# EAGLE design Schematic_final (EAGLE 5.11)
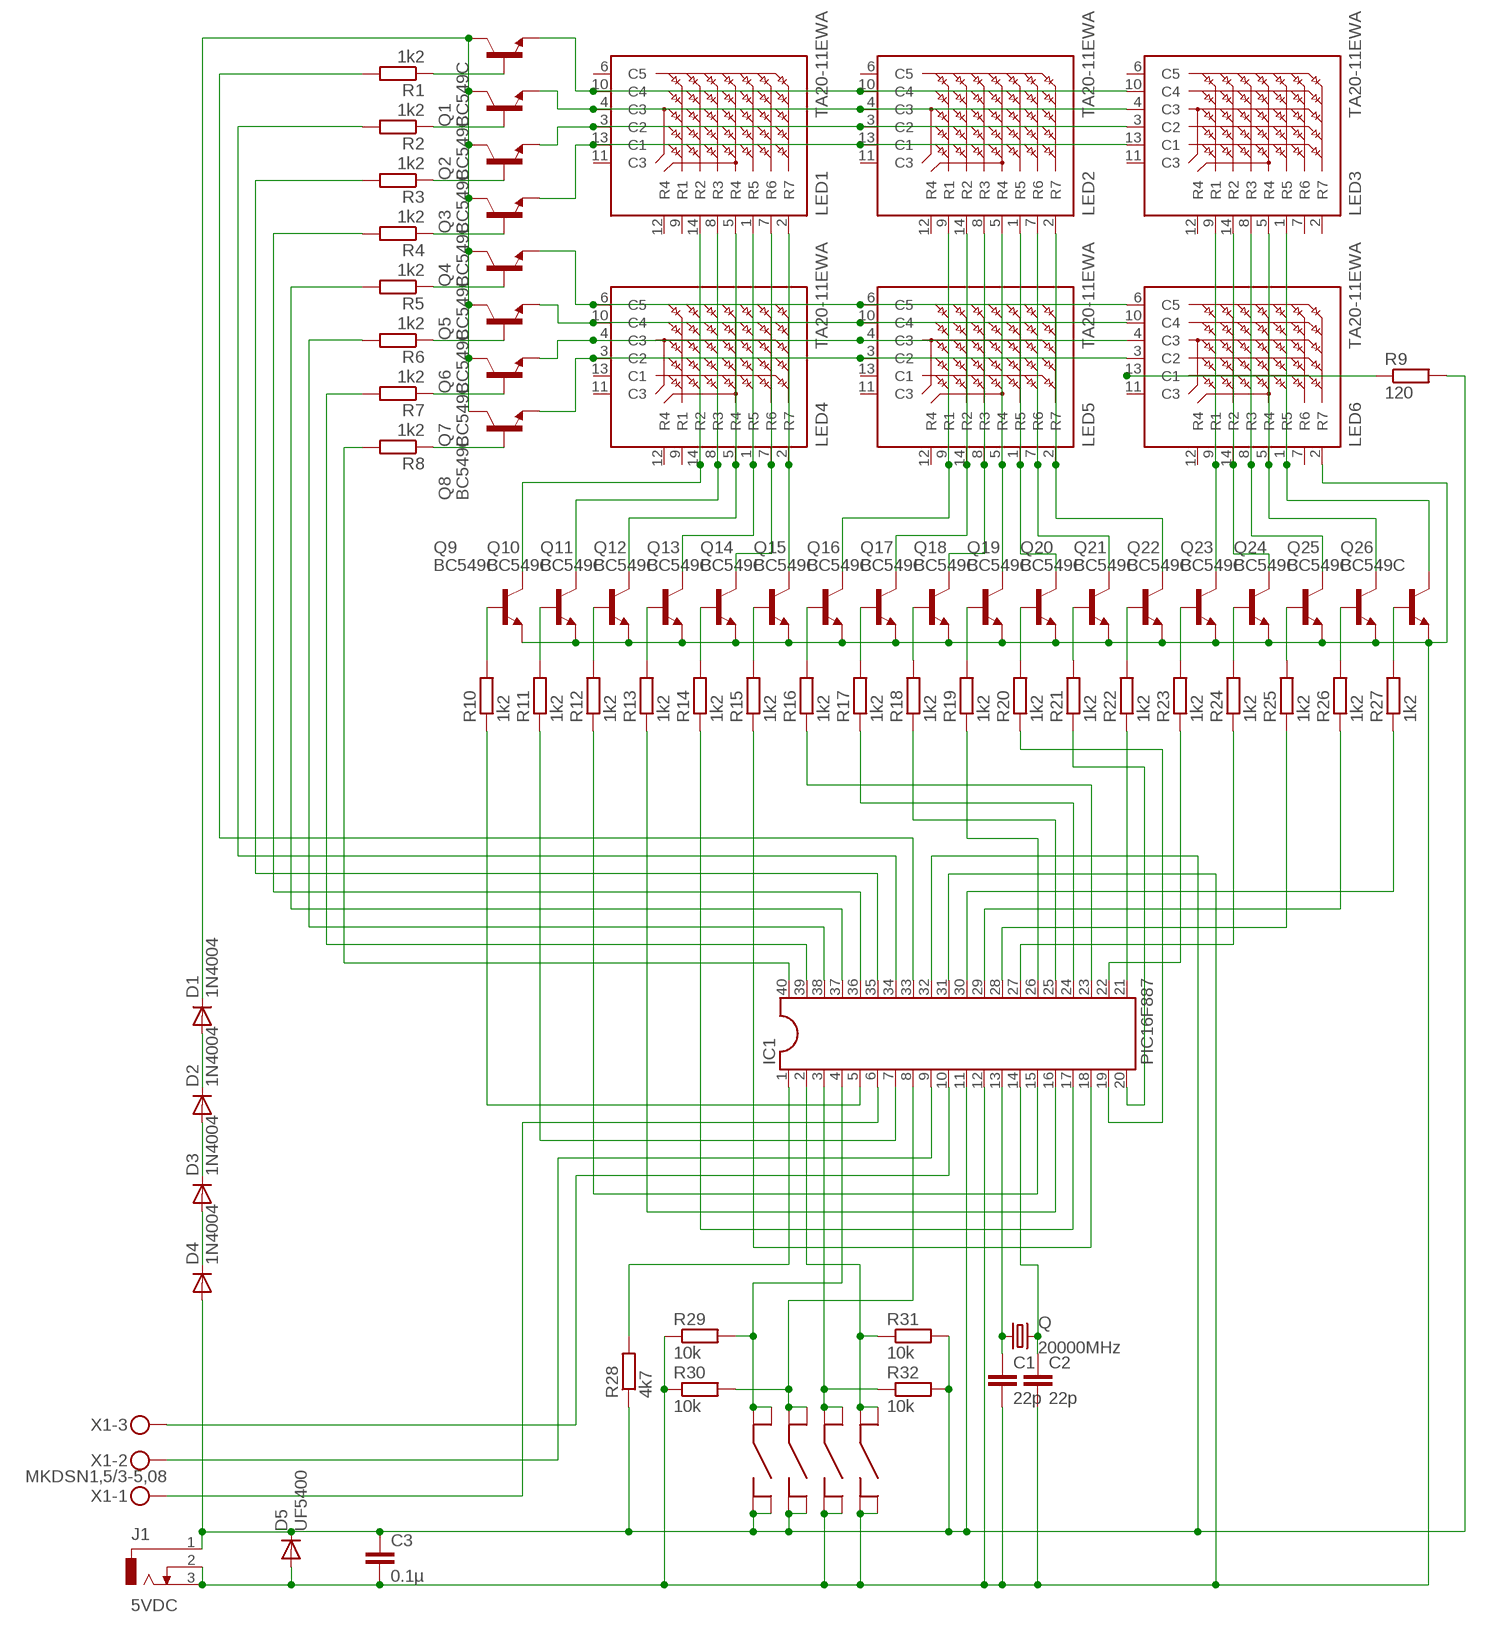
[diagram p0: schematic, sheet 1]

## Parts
C1  22p  C-EU025-025X050  [C025-025X050]
C2  22p  C-EU025-025X050  [C025-025X050]
C3  0.1µ  C-EU050-035X075  [C050-035X075]
D1  1N4004  [DO41-10]
D2  1N4004  [DO41-10]
D3  1N4004  [DO41-10]
D4  1N4004  [DO41-10]
D5  UF5400  [DO201-15]
IC1  PIC16F887  DIL40  [DIL40]
J1  5VDC  DCJ0303  [DCJ0303]
LED1  TA20-11EWA  [TA20-11HWA]
LED2  TA20-11EWA  [TA20-11HWA]
LED3  TA20-11EWA  [TA20-11HWA]
LED4  TA20-11EWA  [TA20-11HWA]
LED5  TA20-11EWA  [TA20-11HWA]
LED6  TA20-11EWA  [TA20-11HWA]
Q  20000MHz  CRYSTALHC49U-V  [HC49U-V]
Q1  BC549C  [TO92-EBC]
Q2  BC549C  [TO92-EBC]
Q3  BC549C  [TO92-EBC]
Q4  BC549C  [TO92-EBC]
Q5  BC549C  [TO92-EBC]
Q6  BC549C  [TO92-EBC]
Q7  BC549C  [TO92-EBC]
Q8  BC549C  [TO92-EBC]
Q9  BC549C  [TO92-EBC]
Q10  BC549C  [TO92-EBC]
Q11  BC549C  [TO92-EBC]
Q12  BC549C  [TO92-EBC]
Q13  BC549C  [TO92-EBC]
Q14  BC549C  [TO92-EBC]
Q15  BC549C  [TO92-EBC]
Q16  BC549C  [TO92-EBC]
Q17  BC549C  [TO92-EBC]
Q18  BC549C  [TO92-EBC]
Q19  BC549C  [TO92-EBC]
Q20  BC549C  [TO92-EBC]
Q21  BC549C  [TO92-EBC]
Q22  BC549C  [TO92-EBC]
Q23  BC549C  [TO92-EBC]
Q24  BC549C  [TO92-EBC]
Q25  BC549C  [TO92-EBC]
Q26  BC549C  [TO92-EBC]
R1  1k2  R-EU_0207/12  [0207/12]
R2  1k2  R-EU_0207/12  [0207/12]
R3  1k2  R-EU_0207/12  [0207/12]
R4  1k2  R-EU_0207/12  [0207/12]
R5  1k2  R-EU_0207/12  [0207/12]
R6  1k2  R-EU_0207/12  [0207/12]
R7  1k2  R-EU_0207/12  [0207/12]
R8  1k2  R-EU_0207/12  [0207/12]
R9  120  R-EU_0207/12  [0207/12]
R10  1k2  R-EU_0207/12  [0207/12]
R11  1k2  R-EU_0207/12  [0207/12]
R12  1k2  R-EU_0207/12  [0207/12]
R13  1k2  R-EU_0207/12  [0207/12]
R14  1k2  R-EU_0207/12  [0207/12]
R15  1k2  R-EU_0207/12  [0207/12]
R16  1k2  R-EU_0207/12  [0207/12]
R17  1k2  R-EU_0207/12  [0207/12]
R18  1k2  R-EU_0207/12  [0207/12]
R19  1k2  R-EU_0207/12  [0207/12]
R20  1k2  R-EU_0207/12  [0207/12]
R21  1k2  R-EU_0207/12  [0207/12]
R22  1k2  R-EU_0207/12  [0207/12]
R23  1k2  R-EU_0207/12  [0207/12]
R24  1k2  R-EU_0207/12  [0207/12]
R25  1k2  R-EU_0207/12  [0207/12]
R26  1k2  R-EU_0207/12  [0207/12]
R27  1k2  R-EU_0207/12  [0207/12]
R28  4k7  R-EU_0207/10  [0207/10]
R29  10k  R-EU_0207/10  [0207/10]
R30  10k  R-EU_0207/10  [0207/10]
R31  10k  R-EU_0207/10  [0207/10]
R32  10k  R-EU_0207/10  [0207/10]
S1  DRUKKNOP  [DRUKKNOP]
S2  DRUKKNOP  [DRUKKNOP]
S3  DRUKKNOP  [DRUKKNOP]
S4  DRUKKNOP  [DRUKKNOP]
X1  MKDSN1,5/3-5,08  [MKDSN1,5/3-5,08]

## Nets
GND: C3.1 D4.A D5.C IC1.11 IC1.32 J1.1 R9.2 R28.1 R31.2 R32.2 S1.P$2 S1.P$4 S2.P$2 S2.P$4
N$1: IC1.5 R10.1
N$2: IC1.7 R11.1
N$3: IC1.16 R13.1
N$4: IC1.15 R12.1
N$5: IC1.17 R14.1
N$6: IC1.18 R15.1
N$7: IC1.23 R16.1
N$8: IC1.24 R17.1
N$9: LED2.5(R4) LED5.5(R4) Q18.C
N$10: LED2.8(R3) LED5.8(R3) Q17.C
N$11: LED2.1(R5) LED5.1(R5) Q19.C
N$12: LED2.14(R2) LED5.14(R2) Q16.C
N$13: LED2.9(R1) LED5.9(R1) Q15.C
N$14: LED2.7(R6) LED5.7(R6) Q20.C
N$15: LED2.2(R7) LED5.2(R7) Q21.C
N$16: LED3.9(R1) LED6.9(R1) Q22.C
N$17: LED3.14(R2) LED6.14(R2) Q23.C
N$18: LED3.8(R3) LED6.8(R3) Q24.C
N$19: LED3.5(R4) LED6.5(R4) Q25.C
N$20: LED3.1(R5) LED6.1(R5) Q26.C
N$21: LED1.2(R7) LED4.2(R7) Q14.C
N$22: LED1.7(R6) LED4.7(R6) Q13.C
N$23: LED1.1(R5) LED4.1(R5) Q12.C
N$24: LED1.5(R4) LED4.5(R4) Q11.C
N$25: LED1.8(R3) LED4.8(R3) Q10.C
N$26: LED1.14(R2) LED4.14(R2) Q9.C
N$27: IC1.25 R18.1
N$28: IC1.19 R20.1
N$29: IC1.20 R21.1
N$30: IC1.26 R19.1
N$31: IC1.21 R22.1
N$32: IC1.22 R23.1
N$33: IC1.27 R24.1
N$34: IC1.28 R25.1
N$35: IC1.29 R26.1
N$36: IC1.30 R27.1
N$37: Q9.B R10.2
N$38: Q17.B R18.2
N$39: Q10.B R11.2
N$40: Q11.B R12.2
N$41: Q12.B R13.2
N$42: Q13.B R14.2
N$43: Q14.B R15.2
N$44: Q15.B R16.2
N$45: Q16.B R17.2
N$46: Q18.B R19.2
N$47: Q19.B R20.2
N$48: Q20.B R21.2
N$49: Q21.B R22.2
N$50: Q22.B R23.2
N$51: Q23.B R24.2
N$52: Q24.B R25.2
N$53: Q25.B R26.2
N$54: Q26.B R27.2
N$55: IC1.1 R28.2
N$56: LED6.13(C1) R9.1
N$57: LED1.10(C4) LED2.10(C4) LED3.10(C4) Q1.E
N$58: LED1.4(C3) LED2.4(C3) LED3.4(C3) Q2.E
N$59: LED1.3(C2) LED2.3(C2) LED3.3(C2) Q3.E
N$60: LED1.13(C1) LED2.13(C1) LED3.13(C1) Q4.E
N$61: LED4.6(C5) LED5.6(C5) LED6.6(C5) Q5.E
N$62: LED4.3(C2) LED5.3(C2) LED6.3(C2) Q8.E
N$63: LED4.4(C3) LED5.4(C3) LED6.4(C3) Q7.E
N$64: LED4.10(C4) LED5.10(C4) LED6.10(C4) Q6.E
N$65: IC1.38 R6.2
N$66: IC1.37 R5.2
N$67: IC1.39 R7.2
N$68: IC1.40 R8.2
N$69: IC1.36 R4.2
N$70: IC1.35 R3.2
N$71: IC1.34 R2.2
N$72: IC1.33 R1.2
N$73: C1.1 IC1.13 Q.1
N$74: IC1.6 X1.1
N$75: C2.1 IC1.14 Q.2
N$76: D1.C Q1.C Q2.C Q3.C Q4.C Q5.C Q6.C Q7.C Q8.C
N$77: D3.A D4.C
N$78: IC1.3 R32.1 S3.P$1 S3.P$3
N$79: IC1.8 R30.2 S2.P$1 S2.P$3
N$80: IC1.4 R29.2 S1.P$1 S1.P$3
N$81: IC1.9 X1.2
N$82: IC1.10 X1.3
N$83: Q1.B R1.1
N$84: Q2.B R2.1
N$85: Q3.B R3.1
N$86: Q4.B R4.1
N$87: Q5.B R5.1
N$88: Q6.B R6.1
N$89: Q7.B R7.1
N$90: Q8.B R8.1
N$91: D1.A D2.C
N$92: D2.A D3.C
N$93: IC1.2 R31.1 S4.P$1 S4.P$3
N$95: C1.2 C2.2 C3.2 D5.A IC1.12 IC1.31 J1.2 J1.3 LED6.2(R7) Q9.E Q10.E Q11.E Q12.E Q13.E Q14.E Q15.E Q16.E Q17.E Q18.E Q19.E Q20.E Q21.E Q22.E Q23.E Q24.E Q25.E Q26.E R29.1 R30.1 S3.P$2 S3.P$4 S4.P$2 S4.P$4
Unconnected: LED1.6(C5) LED1.9(R1) LED1.11(C3) LED1.12(R4) LED2.6(C5) LED2.11(C3) LED2.12(R4) LED3.2(R7) LED3.6(C5) LED3.7(R6) LED3.11(C3) LED3.12(R4) LED4.9(R1) LED4.11(C3) LED4.12(R4) LED4.13(C1) LED5.11(C3) LED5.12(R4) LED5.13(C1) LED6.7(R6) LED6.11(C3) LED6.12(R4)

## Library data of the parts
C1-C3 = resistor:C-EU: CAPACITOR, European symbol
D1-D4 = diode:1N4004: DIODE
D5 = diode:UF5400: DIODE
IC1 = ic-package:DIL40: Dual In Line
J1 = con-jack:DCJ0303: DC POWER JACK Source: DCJ0303.pdf; OC_FARNELL: unknown; OC_NEWARK: unknown
LED1-LED6 = display-kingbright:TA20-11EWA: 50mm (2.0 INCH) 5x7 DOT MATRIX DISPLAY Source: http://www.kingbright.com/manager/upload/pdf/TC20-11EWA(Ver1189410378.9); OC_FARNELL: unknown; OC_NEWARK: unknown
Q = crystal:CRYSTAL: CRYSTAL; OC_FARNELL: 1666969; OC_NEWARK: unknown
Q1-Q26 = transistor-npn:BC549*: NPN Transistor
R1-R32 = resistor:R-EU_: RESISTOR, European symbol
S1-S4 = drukknop:DRUKKNOP: RAFI - 1.14.100.501/0000 - SOLDER TERMINAL, F/PCB, OUTWARD http://www.farnell.com/datasheets/10376.pdf
X1 = con-phoenix-508:MKDSN1,5/3-5,08: MKDSN 1,5/ 3-5,08 Printklemme Nennstrom: 13,5 A Nennspannung: 250 V Rastermaß: 5,08 mm Polzahl: 3 Anschlussart: Schraubanschluss Montage: Löten Anschlussrichtung Leiter/Platine: 0 ° Artikelnummer: 1729131 Source: http://eshop.phoenixcontact.com .. 1729131.pdf; MPN: SMKDSN1,5/3-5,08; OC_FARNELL: 1792904; OC_NEWARK: 70R0299

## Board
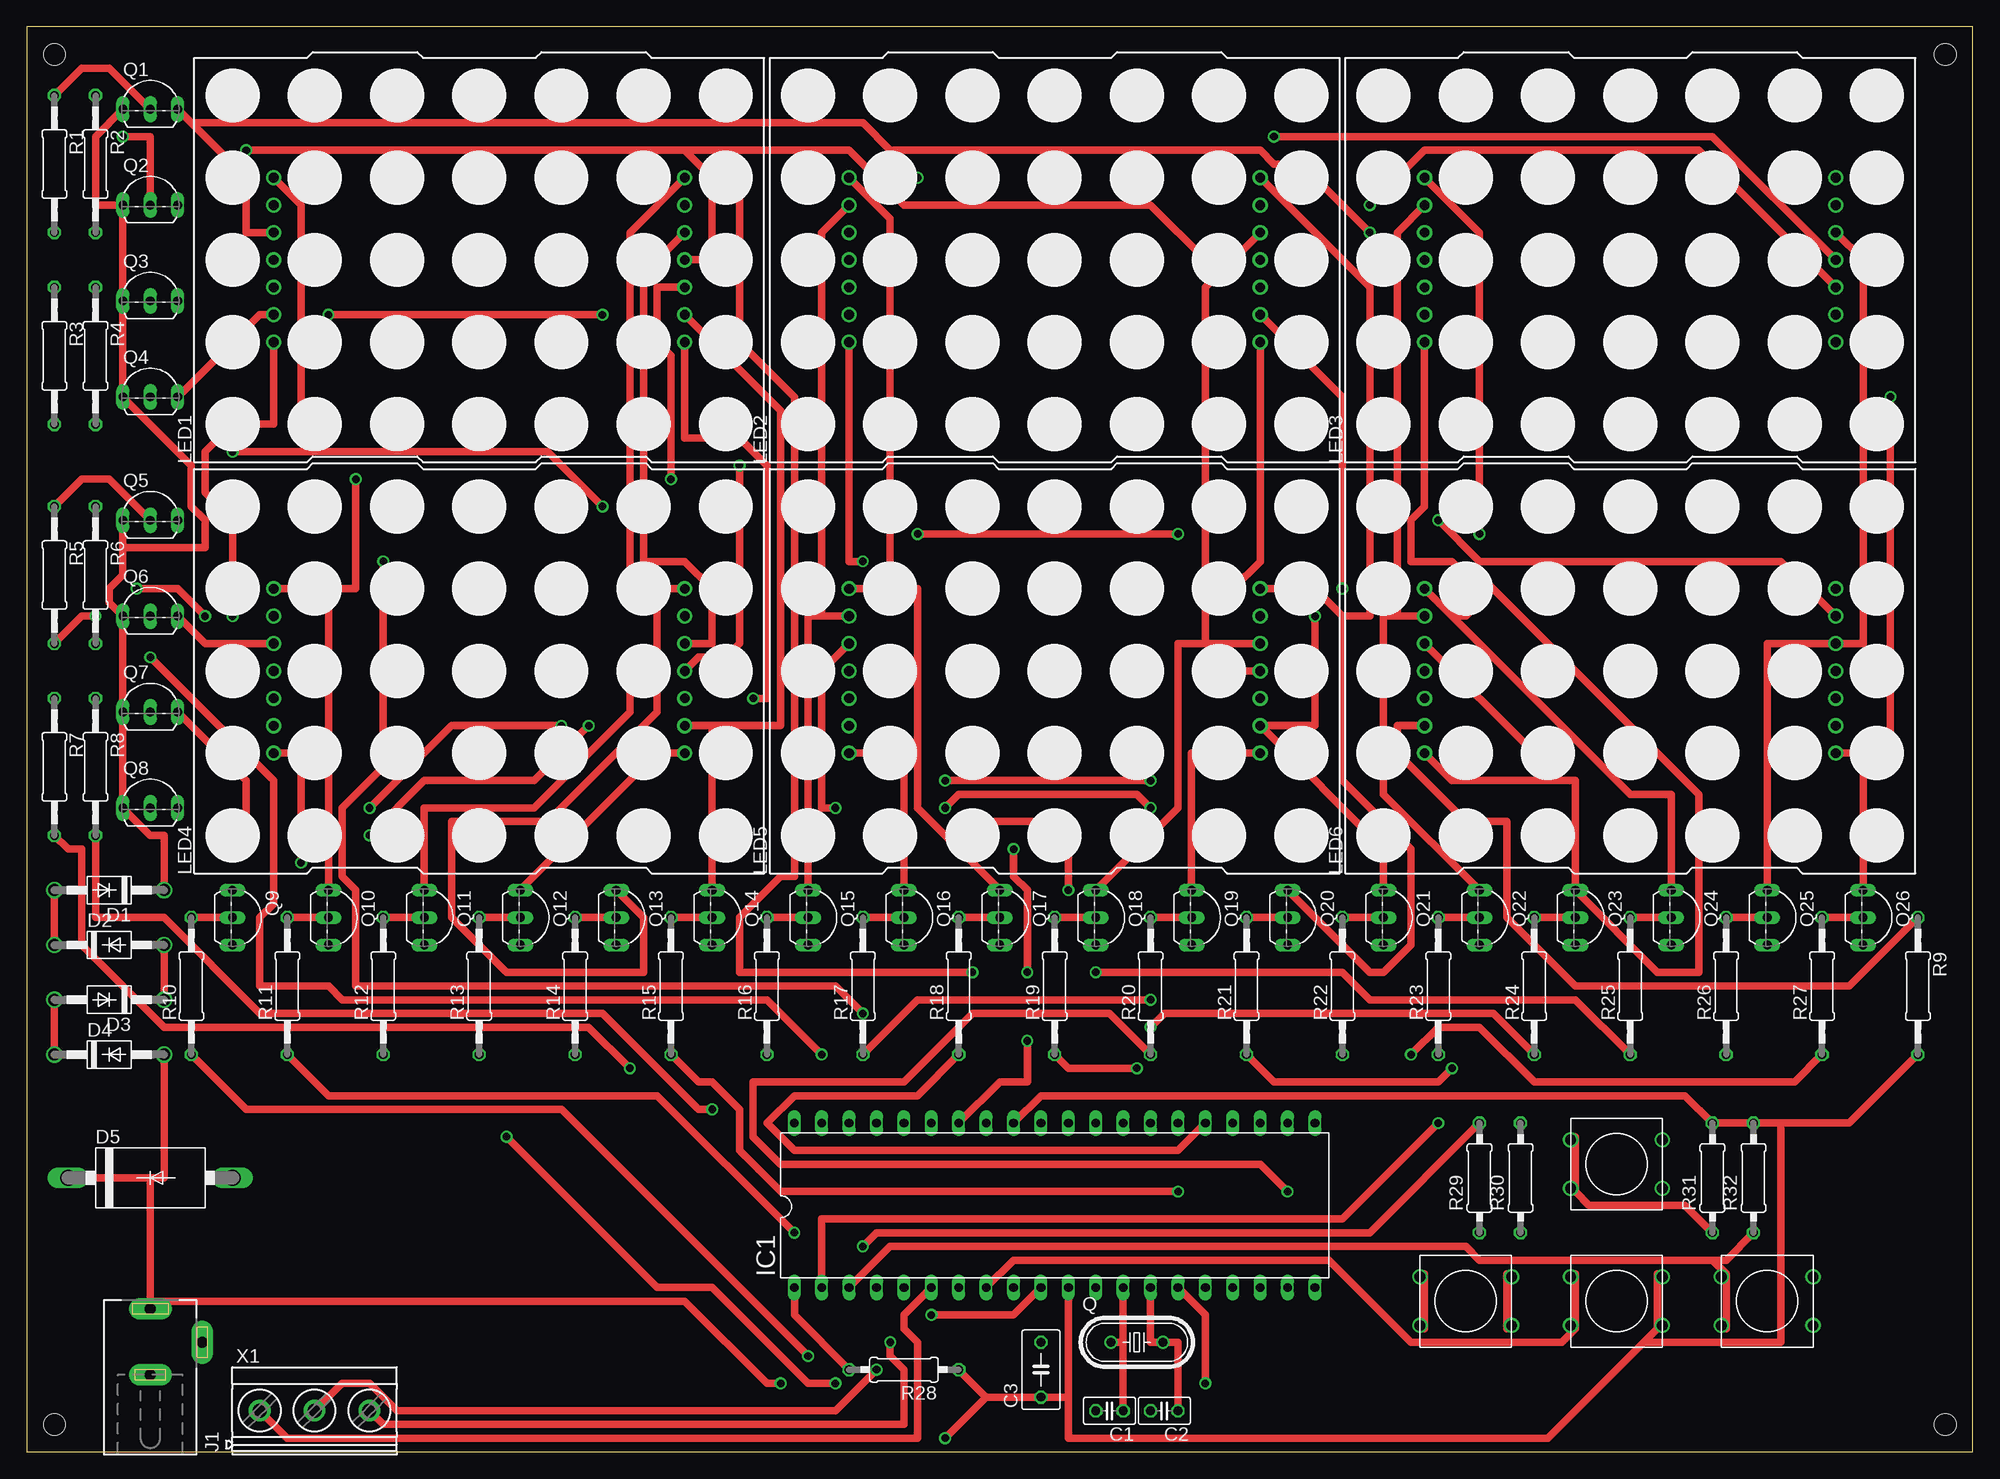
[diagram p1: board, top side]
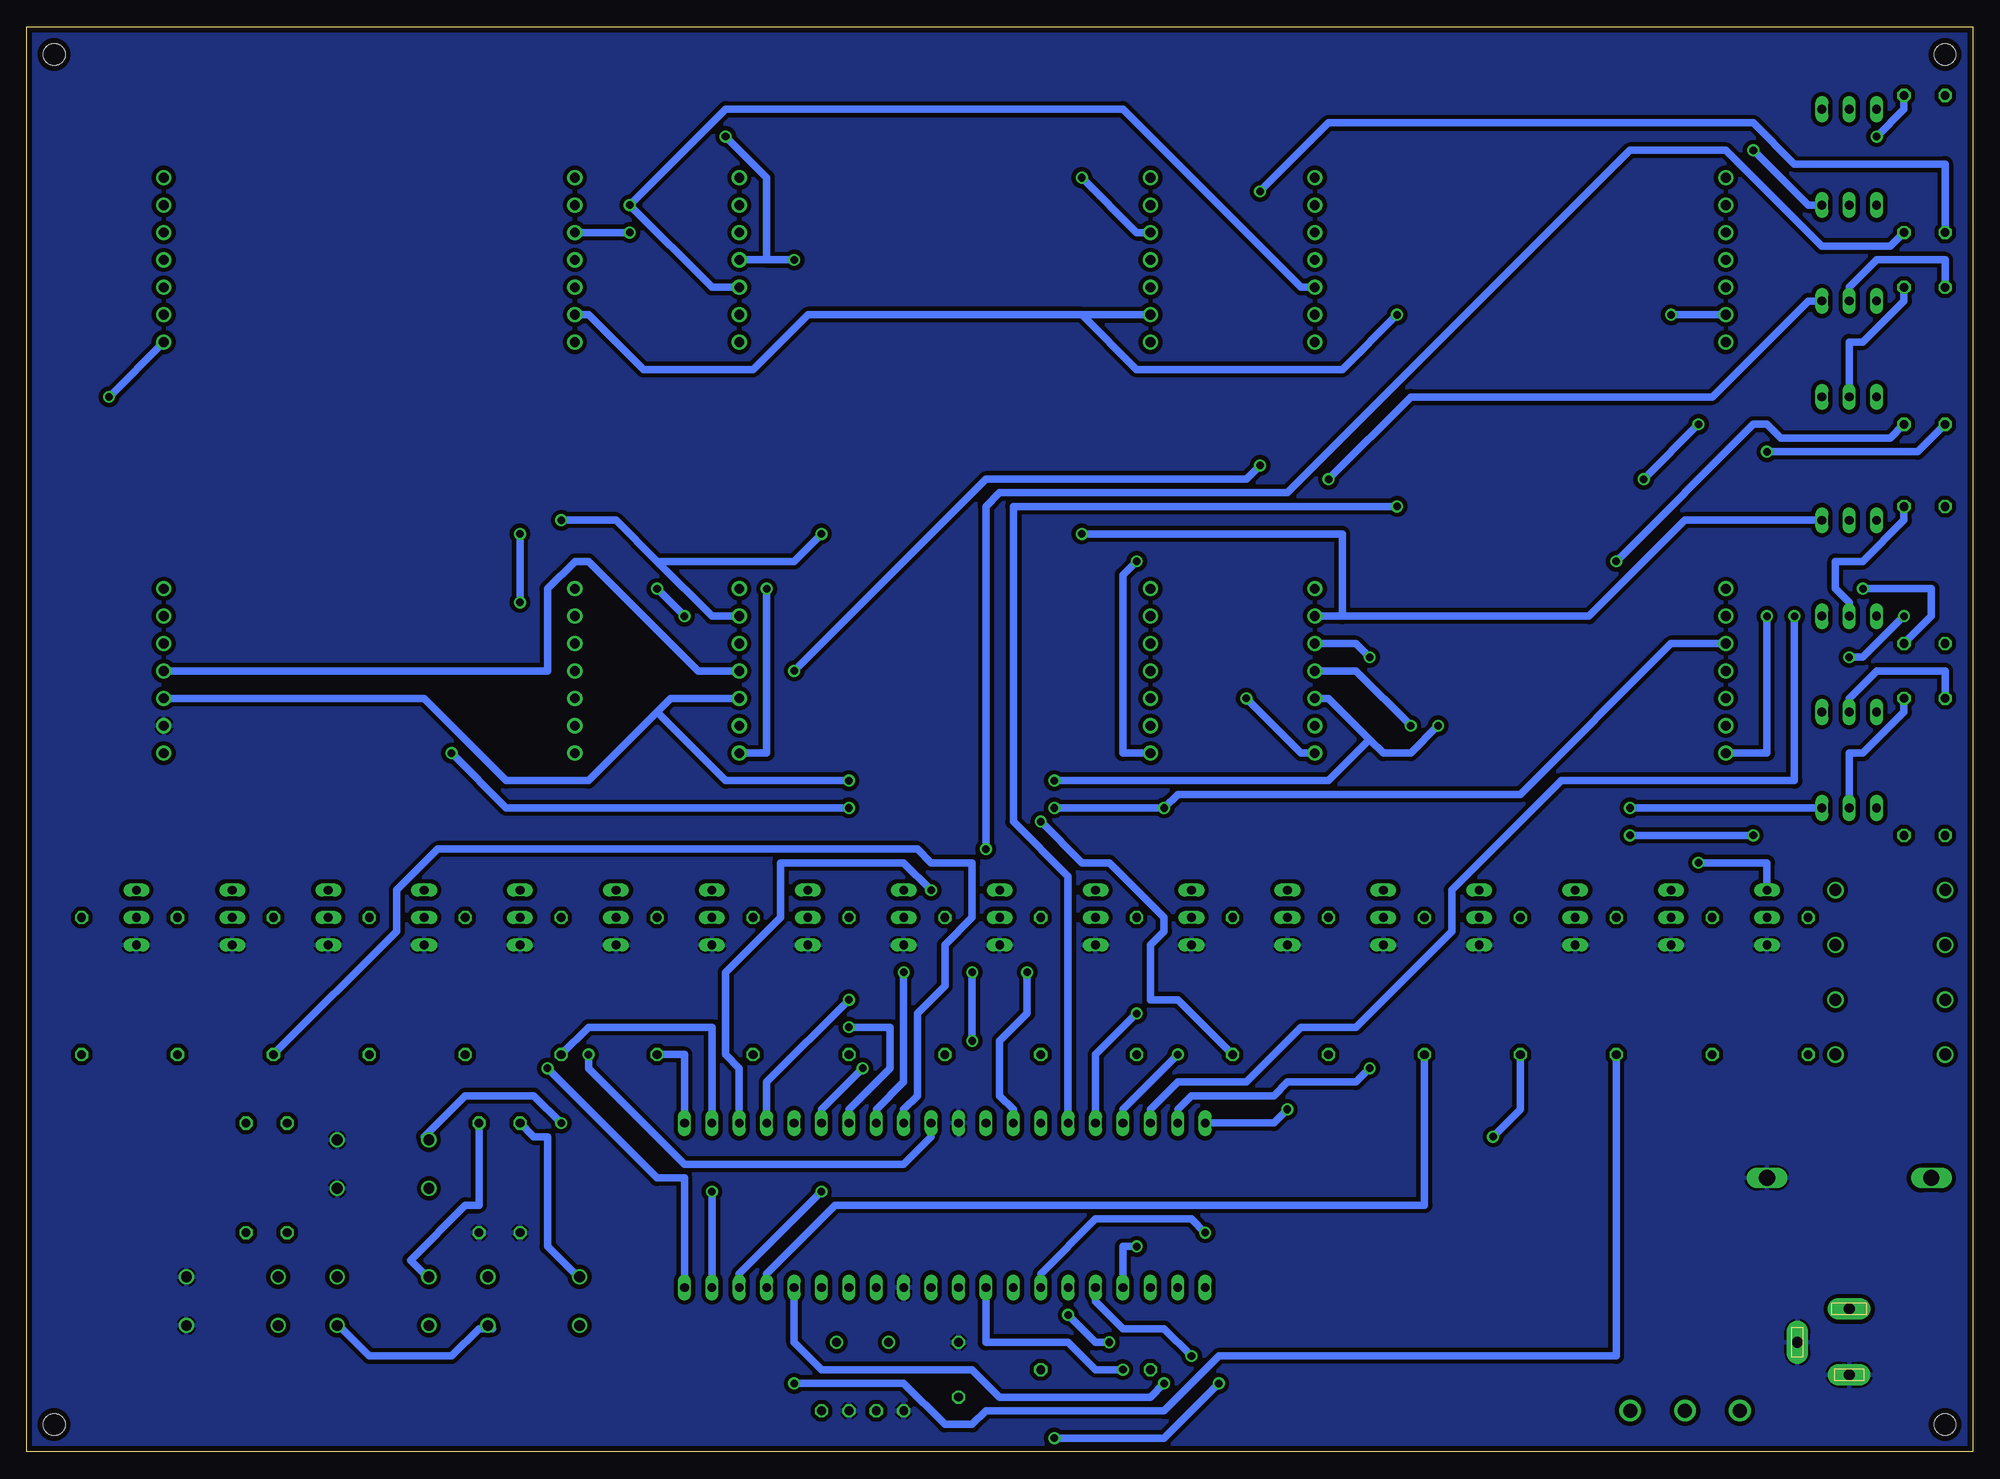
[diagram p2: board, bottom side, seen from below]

Size 180.32 x 132.08 mm. Coordinates in mm from the lower left corner, seen from the top.
Outline: 0,0 180.32,0 180.32,132.08 0,132.08 0,0
Copper layers (1*16): Top 0.018mm / dielectric 1.55mm / Bottom 0.018mm
Design rules "eC-STANDARD_pool-2-layer  *": minimum track width 0.7mm, minimum drill 0.7mm, track to track 0.4mm, track to pad 0.4mm, pad to pad 0.4mm, via to via 0.4mm, smd to smd 0.4mm, copper to edge 0.5mm, drill to drill 0.5mm, minimum pad ring 0.2mm, minimum via ring 0.2mm, stop-mask expansion 0.2mm, vias tented up to drill 0mil, thermal gap 0.2mm
Holes 2 mm at 2.54,2.54 2.54,129.54 177.8,2.54 177.8,129.54

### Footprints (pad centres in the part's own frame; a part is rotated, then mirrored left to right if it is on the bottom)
C025-025X050 = drill 0.813 octagon: 1 -1.27,0; 2 1.27,0
C050-035X075 = drill 0.813 octagon: 1 -2.54,0; 2 2.54,0
DO41-10 = drill 1.118 round: A 5.08,0; C -5.08,0
DO201-15 = drill 1.499 long: A 7.62,0; C -7.62,0
DIL40 = drill 0.813 long: 1 -24.13,-7.62; 2 -21.59,-7.62; 3 -19.05,-7.62; 4 -16.51,-7.62; 5 -13.97,-7.62; 6 -11.43,-7.62; 7 -8.89,-7.62; 8 -6.35,-7.62; 9 -3.81,-7.62; 10 -1.27,-7.62; 11 1.27,-7.62; 12 3.81,-7.62; 13 6.35,-7.62; 14 8.89,-7.62; 15 11.43,-7.62; 16 13.97,-7.62; 17 16.51,-7.62; 18 19.05,-7.62; 19 21.59,-7.62; 20 24.13,-7.62; 21 24.13,7.62; 22 21.59,7.62; 23 19.05,7.62; 24 16.51,7.62; 25 13.97,7.62; 26 11.43,7.62; 27 8.89,7.62; 28 6.35,7.62; 29 3.81,7.62; 30 1.27,7.62; 31 -1.27,7.62; 32 -3.81,7.62; 33 -6.35,7.62; 34 -8.89,7.62; 35 -11.43,7.62; 36 -13.97,7.62; 37 -16.51,7.62; 38 -19.05,7.62; 39 -21.59,7.62; 40 -24.13,7.62
DCJ0303 = drill 1 pad 2 long: 1 0,3.1; 2 4.8,0; 3 0,-3
TA20-11HWA = drill 0.9 pad 1.4 round: 1 -7.62,-19.05; 2 -5.08,-19.05; 3 -2.54,-19.05; 4 0,-19.05; 5 2.54,-19.05; 6 5.08,-19.05; 7 7.62,-19.05; 8 7.62,19.05; 9 5.08,19.05; 10 2.54,19.05; 11 0,19.05; 12 -2.54,19.05; 13 -5.08,19.05; 14 -7.62,19.05
HC49U-V = drill 0.813 round: 1 -2.413,0; 2 2.413,0
TO92-EBC = drill 0.813 long: B 0,-1.27; C -2.54,-1.27; E 2.54,-1.27
0207/12 = drill 0.813 octagon: 1 -6.35,0; 2 6.35,0
0207/10 = drill 0.813 octagon: 1 -5.08,0; 2 5.08,0
DRUKKNOP = drill 1 round: P$1 -4.25,2.25; P$2 4.25,2.25; P$3 -4.25,-2.25; P$4 4.25,-2.25
MKDSN1,5/3-5,08 = drill 1.3 pad 2 round: 1 -7.641,0.025; 2 -2.561,0.025; 3 2.519,0.025

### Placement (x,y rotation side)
C1  100.33,3.81 180 top
C2  105.41,3.81 180 top
C3  93.98,7.62 90 top
D1  7.62,52.07 180 top
D2  7.62,46.99 0 top
D3  7.62,41.91 180 top
D4  7.62,36.83 0 top
D5  11.43,25.4 0 top
IC1  95.25,22.86 0 top
J1  11.43,10.16 0 top
LED1  41.91,110.49 90 top
LED2  95.25,110.49 90 top
LED3  148.59,110.49 90 top
LED4  41.91,72.39 90 top
LED5  95.25,72.39 90 top
LED6  148.59,72.39 90 top
Q  102.87,10.16 0 top
Q1  11.43,125.73 0 top
Q2  11.43,116.84 0 top
Q3  11.43,107.95 0 top
Q4  11.43,99.06 0 top
Q5  11.43,87.63 0 top
Q6  11.43,78.74 0 top
Q7  11.43,69.85 0 top
Q8  11.43,60.96 0 top
Q9  20.32,49.53 270 top
Q10  29.21,49.53 270 top
Q11  38.1,49.53 270 top
Q12  46.99,49.53 270 top
Q13  55.88,49.53 270 top
Q14  64.77,49.53 270 top
Q15  73.66,49.53 270 top
Q16  82.55,49.53 270 top
Q17  91.44,49.53 270 top
Q18  100.33,49.53 270 top
Q19  109.22,49.53 270 top
Q20  118.11,49.53 270 top
Q21  127,49.53 270 top
Q22  135.89,49.53 270 top
Q23  144.78,49.53 270 top
Q24  153.67,49.53 270 top
Q25  162.56,49.53 270 top
Q26  171.45,49.53 270 top
R1  2.54,119.38 270 top
R2  6.35,119.38 270 top
R3  2.54,101.6 270 top
R4  6.35,101.6 270 top
R5  2.54,81.28 270 top
R6  6.35,81.28 270 top
R7  2.54,63.5 270 top
R8  6.35,63.5 270 top
R9  175.26,43.18 270 top
R10  15.24,43.18 90 top
R11  24.13,43.18 90 top
R12  33.02,43.18 90 top
R13  41.91,43.18 90 top
R14  50.8,43.18 90 top
R15  59.69,43.18 90 top
R16  68.58,43.18 90 top
R17  77.47,43.18 90 top
R18  86.36,43.18 90 top
R19  95.25,43.18 90 top
R20  104.14,43.18 90 top
R21  113.03,43.18 90 top
R22  121.92,43.18 90 top
R23  130.81,43.18 90 top
R24  139.7,43.18 90 top
R25  148.59,43.18 90 top
R26  157.48,43.18 90 top
R27  166.37,43.18 90 top
R28  81.28,7.62 180 top
R29  134.62,25.4 90 top
R30  138.43,25.4 90 top
R31  156.21,25.4 90 top
R32  160.02,25.4 90 top
S1  133.35,13.97 0 top
S2  147.32,13.97 0 top
S3  161.29,13.97 0 top
S4  147.32,26.67 0 top
X1  29.21,3.81 0 top

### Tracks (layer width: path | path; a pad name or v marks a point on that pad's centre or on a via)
GND  (via drill 0.7)
  Top 0.7: IC1.32 93.98,33.02 153.67,33.02 R31.2 R32.2 162.56,30.48 | R9.2 168.91,30.48 162.56,30.48 | D4.A 12.7,25.4 11.43,25.4 | 11.43,25.4 D5.C | 11.43,13.97 11.43,25.4 | 88.9,5.08 R28.1 | 88.9,5.08 C3.1 96.52,5.08 | 96.52,5.08 IC1.11 | S1.P$4 137.16,11.43 137.16,16.51 S1.P$2 | 151.13,11.43 151.13,16.51 S2.P$2 | 96.52,5.08 96.52,1.27 140.97,1.27 149.86,10.16 | 149.86,10.16 151.13,11.43 | 151.13,11.43 S2.P$4 | 11.43,13.97 60.96,13.97 68.58,6.35 v69.85,6.35 | v85.09,1.27 88.9,5.08 | J1.1 11.43,13.97 | 162.56,30.48 162.56,10.16 149.86,10.16
  Bottom 0.7: S1.P$4 137.16,11.43 138.43,11.43 140.97,8.89 148.59,8.89 151.13,11.43 S2.P$4 | v69.85,6.35 74.93,1.27 v85.09,1.27
N$1  (via drill 0.7)
  Top 0.7: R10.1 20.32,31.75 49.53,31.75 v72.39,8.89
  Bottom 0.7: v72.39,8.89 74.93,11.43 78.74,11.43 81.28,13.97 IC1.5
N$2  (via drill 0.7)
  Top 0.7: R11.1 27.94,33.02 58.42,33.02 v71.12,20.32
  Bottom 0.7: v71.12,20.32 72.39,21.59 81.28,21.59 86.36,16.51 IC1.7
N$3  (via drill 0.7)
  Top 0.7: v44.45,29.21 58.42,15.24 63.5,15.24 72.39,6.35 v74.93,6.35
  Bottom 0.7: R13.1 41.91,31.75 v44.45,29.21 | v74.93,6.35 76.2,5.08 90.17,5.08 92.71,7.62 106.68,7.62 109.22,10.16 IC1.16
N$4  (via drill 0.7)
  Top 0.7: v109.22,6.35 109.22,12.7 IC1.15
  Bottom 0.7: R12.1 33.02,8.89 69.85,8.89 74.93,3.81 91.44,3.81 92.71,2.54 95.25,2.54 99.06,6.35 v109.22,6.35
N$5
  Bottom 0.7: R14.1 50.8,22.86 105.41,22.86 111.76,16.51 IC1.17
N$6  (via drill 0.7)
  Top 0.7: R15.1 62.23,34.29 63.5,34.29 66.04,31.75 66.04,27.94 69.85,24.13 v106.68,24.13
  Bottom 0.7: v106.68,24.13 114.3,16.51 IC1.18
N$7  (via drill 0.7)
  Top 0.7: v96.52,52.07 96.52,58.42 v86.36,58.42
  Bottom 0.7: IC1.23 114.3,35.56 115.57,36.83 115.57,44.45 110.49,49.53 110.49,54.61 99.06,54.61 v96.52,52.07 | v86.36,58.42 82.55,54.61 80.01,54.61 74.93,49.53 74.93,48.26 76.2,46.99 76.2,41.91 73.66,41.91 R16.1
N$8  (via drill 0.7)
  Top 0.7: R17.1 82.55,41.91 v104.14,41.91
  Bottom 0.7: v104.14,41.91 111.76,34.29 IC1.24
N$9
  Top 0.7: Q18.C 106.68,59.69 106.68,74.93 109.22,74.93 | 109.22,74.93 LED5.5 | LED2.5 109.22,107.95 109.22,74.93
N$10
  Top 0.7: Q17.C 82.55,59.69 82.55,80.01 80.01,80.01 | 80.01,80.01 LED5.8 | LED2.8 80.01,114.3 80.01,80.01
N$11  (via drill 0.7)
  Top 0.7: Q19.C 107.95,64.77 LED5.1 | LED2.1 114.3,82.55 v111.76,80.01
  Bottom 0.7: v111.76,80.01 111.76,64.77 LED5.1
N$12  (via drill 0.7)
  Top 0.7: Q16.C 81.28,64.77 LED5.14 | LED2.14 76.2,82.55 v77.47,82.55
  Bottom 0.7: v77.47,82.55 78.74,81.28 78.74,64.77 LED5.14
N$13
  Top 0.7: Q15.C 72.39,77.47 73.66,77.47 | 73.66,77.47 LED5.9 | LED2.9 73.66,113.03 73.66,77.47
N$14
  Top 0.7: Q20.C 124.46,44.45 125.73,44.45 128.27,46.99 128.27,55.88 121.92,62.23 121.92,77.47 | 121.92,77.47 119.38,80.01 LED5.7 | LED2.7 124.46,107.95 124.46,77.47 121.92,77.47
N$15  (via drill 0.7)
  Top 0.7: Q21.C 125.73,55.88 LED5.2 119.38,67.31 v119.38,77.47 | LED2.2 121.92,97.79 v121.92,80.01
  Bottom 0.7: v119.38,77.47 v121.92,80.01
N$16
  Top 0.7: Q22.C 125.73,60.96 125.73,77.47 127,77.47 | 127,77.47 LED6.9 | LED3.9 127,113.03 127,77.47
N$17
  Top 0.7: LED6.14 132.08,62.23 143.51,62.23 Q23.C 151.13,44.45 154.94,44.45 154.94,60.96 134.62,81.28 133.35,81.28 132.08,82.55 128.27,82.55 128.27,86.36 129.54,87.63 LED3.14
N$18  (via drill 0.7)
  Top 0.7: Q24.C 152.4,60.96 148.59,60.96 132.08,77.47 | 132.08,77.47 LED6.8 | LED3.8 134.62,113.03 v134.62,85.09 | v134.62,78.74 133.35,77.47 132.08,77.47
  Bottom 0.7: v134.62,78.74 v134.62,85.09
N$19
  Top 0.7: Q25.C 161.29,74.93 LED6.5 170.18,74.93 170.18,110.49 LED3.5
N$20  (via drill 0.7)
  Top 0.7: 170.18,64.77 Q26.C | 170.18,64.77 LED6.1 | v172.72,97.79 172.72,64.77 170.18,64.77
  Bottom 0.7: LED3.1 v172.72,97.79
N$21
  Top 0.7: Q14.C 63.5,67.31 | 63.5,67.31 LED4.2 | LED1.2 69.85,96.52 69.85,67.31 63.5,67.31
N$22
  Top 0.7: Q13.C 57.15,49.53 57.15,44.45 44.45,44.45 39.37,49.53 39.37,58.42 48.26,58.42 58.42,68.58 58.42,80.01 | 58.42,80.01 LED4.7 | LED1.7 55.88,113.03 55.88,80.01 58.42,80.01
N$23  (via drill 0.7)
  Top 0.7: Q12.C 58.42,64.77 LED4.1 | LED1.1 60.96,93.98 66.04,93.98 68.58,91.44 68.58,69.85 v67.31,69.85
  Bottom 0.7: v67.31,69.85 62.23,64.77 LED4.1
N$24  (via drill 0.7)
  Top 0.7: Q11.C 36.83,59.69 46.99,59.69 55.88,68.58 v55.88,73.66 | LED1.5 57.15,109.22 57.15,82.55 60.96,82.55 63.5,80.01 63.5,74.93 LED4.5
  Bottom 0.7: v55.88,73.66 57.15,74.93 LED4.5
N$25  (via drill 0.7)
  Top 0.7: Q10.C 27.94,80.01 | 27.94,80.01 LED4.8 | LED1.8 25.4,115.57 v25.4,95.25 | v30.48,90.17 30.48,80.01 27.94,80.01
  Bottom 0.7: v30.48,90.17 v25.4,95.25
N$26  (via drill 0.7)
  Top 0.7: v25.4,54.61 25.4,64.77 LED4.14 | LED1.14 22.86,95.25 19.05,95.25 16.51,92.71 16.51,88.9 19.05,86.36 v19.05,77.47
  Bottom 0.7: Q9.C 19.05,54.61 v25.4,54.61 | v19.05,77.47 19.05,64.77 LED4.14
N$27
  Top 0.7: R18.1 82.55,33.02 71.12,33.02 68.58,30.48 71.12,27.94 106.68,27.94 IC1.25
N$28  (via drill 0.7)
  Top 0.7: v116.84,24.13 114.3,26.67 69.85,26.67 67.31,29.21 67.31,34.29 81.28,34.29 87.63,40.64 100.33,40.64 R20.1
  Bottom 0.7: v116.84,24.13 IC1.19
N$29  (via drill 0.7)
  Top 0.7: v132.08,35.56 130.81,34.29 115.57,34.29 R21.1
  Bottom 0.7: IC1.20 119.38,25.4 121.92,25.4 v132.08,35.56
N$30  (via drill 0.7)
  Top 0.7: R19.1 96.52,35.56 v102.87,35.56
  Bottom 0.7: v102.87,35.56 106.68,31.75 IC1.26
N$31
  Bottom 0.7: IC1.21 119.38,36.83 R22.1
N$32
  Bottom 0.7: IC1.22 116.84,39.37 128.27,39.37 R23.1
N$33  (via drill 0.7)
  Top 0.7: v104.14,39.37 105.41,40.64 135.89,40.64 R24.1
  Bottom 0.7: IC1.27 104.14,31.75 100.33,35.56 100.33,39.37 v104.14,39.37
N$34  (via drill 0.7)
  Top 0.7: v99.06,44.45 121.92,44.45 124.46,41.91 143.51,41.91 R25.1
  Bottom 0.7: IC1.28 101.6,31.75 99.06,34.29 v99.06,44.45
N$35
  Bottom 0.7: IC1.29 99.06,31.75 97.79,33.02 97.79,40.64 95.25,43.18 95.25,46.99 92.71,49.53 92.71,54.61 96.52,54.61 97.79,55.88 142.24,55.88 146.05,52.07 146.05,48.26 R26.1
N$36  (via drill 0.7)
  Top 0.7: v128.27,36.83 130.81,39.37 134.62,39.37 139.7,34.29 163.83,34.29 R27.1
  Bottom 0.7: IC1.30 96.52,29.21 99.06,26.67 119.38,26.67 128.27,35.56 v128.27,36.83
N$37
  Top 0.7: R10.2 Q9.B
N$38
  Top 0.7: R18.2 Q17.B
N$39
  Top 0.7: R11.2 Q10.B
N$40
  Top 0.7: R12.2 Q11.B
N$41
  Top 0.7: R13.2 Q12.B
N$42
  Top 0.7: R14.2 Q13.B
N$43
  Top 0.7: R15.2 Q14.B
N$44
  Top 0.7: R16.2 Q15.B
N$45
  Top 0.7: R17.2 Q16.B
N$46
  Top 0.7: R19.2 Q18.B
N$47
  Top 0.7: R20.2 Q19.B
N$48
  Top 0.7: R21.2 Q20.B
N$49
  Top 0.7: R22.2 Q21.B
N$50
  Top 0.7: R23.2 Q22.B
N$51
  Top 0.7: R24.2 Q23.B
N$52
  Top 0.7: R25.2 Q24.B
N$53
  Top 0.7: R26.2 Q25.B
N$54
  Top 0.7: R27.2 Q26.B
N$55
  Top 0.7: R28.2 71.12,12.7 IC1.1
N$56
  Top 0.7: R9.1 168.91,43.18 143.51,43.18 137.16,49.53 137.16,58.42 133.35,58.42 127,64.77 127,67.31 LED6.13
N$57  (via drill 0.7)
  Top 0.7: 15.24,123.19 20.32,118.11 20.32,113.03 LED1.10 | 15.24,123.19 Q1.E | 80.01,120.65 77.47,123.19 15.24,123.19 | 80.01,120.65 v82.55,118.11 | v124.46,113.03 118.11,119.38 115.57,119.38 114.3,120.65 80.01,120.65
  Bottom 0.7: LED2.10 77.47,113.03 v82.55,118.11 | v124.46,113.03 LED3.10
N$58  (via drill 0.7)
  Top 0.7: 60.96,120.65 v20.32,120.65 | 60.96,120.65 63.5,118.11 63.5,110.49 LED1.4 | v109.22,110.49 104.14,115.57 81.28,115.57 76.2,120.65 60.96,120.65 | LED3.4 156.21,121.92 v115.57,121.92
  Bottom 0.7: Q2.E 15.24,115.57 v20.32,120.65 | 111.76,110.49 v109.22,110.49 | 111.76,110.49 LED2.4 | v115.57,121.92 111.76,118.11 111.76,110.49
N$59  (via drill 0.7)
  Top 0.7: v59.69,90.17 59.69,101.6 58.42,102.87 58.42,107.95 LED1.3 | v124.46,115.57 129.54,120.65 154.94,120.65 LED3.3
  Bottom 0.7: Q3.E 15.24,106.68 24.13,97.79 52.07,97.79 v59.69,90.17 | LED2.3 116.84,107.95 v124.46,115.57 115.57,124.46 78.74,124.46 62.23,107.95 LED1.3
N$60  (via drill 0.7)
  Top 0.7: Q4.E 21.59,105.41 LED1.13 | v27.94,105.41 v53.34,105.41
  Bottom 0.7: 82.55,105.41 107.95,105.41 113.03,100.33 123.19,100.33 128.27,105.41 LED3.13 | 82.55,105.41 LED2.13 | LED1.13 v27.94,105.41 | v53.34,105.41 58.42,100.33 77.47,100.33 82.55,105.41
N$61  (via drill 0.7)
  Top 0.7: v130.81,86.36 134.62,82.55 162.56,82.55 LED6.6 | v82.55,85.09 v106.68,85.09
  Bottom 0.7: Q5.E 26.67,86.36 35.56,77.47 58.42,77.47 | 58.42,77.47 LED4.6 | LED5.6 116.84,77.47 121.92,82.55 | 121.92,82.55 125.73,86.36 v130.81,86.36 | 58.42,77.47 58.42,85.09 v82.55,85.09 | v106.68,85.09 109.22,82.55 121.92,82.55
N$62  (via drill 0.7)
  Top 0.7: v31.75,59.69 39.37,67.31 v49.53,67.31 | v85.09,62.23 v104.14,62.23
  Bottom 0.7: Q8.E v31.75,59.69 | v49.53,67.31 52.07,64.77 54.61,64.77 55.88,66.04 | 55.88,66.04 59.69,69.85 LED4.3 | LED5.3 120.65,69.85 121.92,68.58 | 121.92,68.58 128.27,62.23 135.89,62.23 143.51,69.85 LED6.3 | 55.88,66.04 59.69,62.23 v85.09,62.23 | v104.14,62.23 115.57,62.23 121.92,68.58
N$63  (via drill 0.7)
  Top 0.7: Q7.E 20.32,62.23 v20.32,57.15 | v31.75,57.15 36.83,62.23 46.99,62.23 v52.07,67.31 | LED4.4 62.23,73.66 64.77,73.66 66.04,74.93 v66.04,91.44 | v109.22,72.39 LED5.4
  Bottom 0.7: v20.32,57.15 v31.75,57.15 | v52.07,67.31 57.15,72.39 LED4.4 | LED5.4 118.11,72.39 128.27,82.55 129.54,82.55 132.08,80.01 132.08,72.39 LED6.4 | v66.04,91.44 67.31,90.17 91.44,90.17 v109.22,72.39
N$64  (via drill 0.7)
  Top 0.7: Q6.E 16.51,74.93 LED4.10 | LED5.10 73.66,72.39 73.66,59.69 v74.93,59.69 | LED6.10 139.7,64.77 v140.97,64.77 | v104.14,59.69 102.87,60.96 86.36,60.96 v85.09,59.69
  Bottom 0.7: LED4.10 27.94,74.93 41.91,60.96 73.66,60.96 v74.93,59.69 v85.09,59.69 | v140.97,64.77 135.89,59.69 v104.14,59.69
N$65  (via drill 0.7)
  Top 0.7: v10.16,80.01 13.97,80.01 v16.51,77.47
  Bottom 0.7: R6.2 3.81,77.47 3.81,80.01 v10.16,80.01 | v16.51,77.47 16.51,62.23 38.1,62.23 48.26,52.07 48.26,48.26 57.15,39.37 62.23,39.37 67.31,34.29 73.66,34.29 76.2,31.75 IC1.38
N$66  (via drill 0.7)
  Top 0.7: R5.2 5.08,77.47 v6.35,77.47 | v11.43,73.66 22.86,62.23 22.86,50.8 21.59,49.53 21.59,43.18 27.94,43.18 29.21,41.91 68.58,41.91 v73.66,36.83
  Bottom 0.7: v6.35,77.47 10.16,73.66 v11.43,73.66 | v73.66,36.83 78.74,31.75 IC1.37
N$67  (via drill 0.7)
  Top 0.7: v55.88,35.56 52.07,39.37 12.7,39.37 5.08,46.99 5.08,55.88 3.81,55.88 R7.2
  Bottom 0.7: IC1.39 73.66,31.75 72.39,33.02 64.77,33.02 63.5,34.29 57.15,34.29 v55.88,35.56
N$68  (via drill 0.7)
  Top 0.7: R8.2 6.35,49.53 12.7,49.53 21.59,40.64 53.34,40.64 62.23,31.75 v63.5,31.75
  Bottom 0.7: v63.5,31.75 64.77,30.48 IC1.40
N$69  (via drill 0.7)
  Top 0.7: v33.02,82.55 33.02,63.5 29.21,59.69 29.21,53.34 30.48,52.07 30.48,43.18 74.93,43.18 v77.47,40.64
  Bottom 0.7: R4.2 7.62,93.98 17.78,93.98 19.05,95.25 20.32,95.25 v33.02,82.55 | v77.47,40.64 81.28,36.83 IC1.36
N$70  (via drill 0.7)
  Top 0.7: v53.34,87.63 48.26,92.71 v19.05,92.71
  Bottom 0.7: IC1.35 83.82,53.34 88.9,58.42 88.9,87.63 v53.34,87.63 | v19.05,92.71 5.08,92.71 R3.2
N$71  (via drill 0.7)
  Top 0.7: v91.44,55.88 91.44,53.34 92.71,52.07 v92.71,44.45 | v92.71,38.1 92.71,34.29 90.17,34.29 IC1.34
  Bottom 0.7: R2.2 7.62,111.76 13.97,111.76 22.86,120.65 31.75,120.65 63.5,88.9 90.17,88.9 91.44,87.63 v91.44,55.88 | v92.71,44.45 v92.71,38.1
N$72  (via drill 0.7)
  Top 0.7: v66.04,116.84 66.04,102.87 71.12,97.79 71.12,53.34 69.85,53.34 66.04,49.53 66.04,44.45 v87.63,44.45
  Bottom 0.7: R1.2 2.54,119.38 16.51,119.38 20.32,123.19 59.69,123.19 v66.04,116.84 | v87.63,44.45 87.63,40.64 90.17,38.1 90.17,33.02 88.9,31.75 IC1.33
N$73
  Top 0.7: C1.1 101.6,10.16 | 101.6,10.16 Q.1 100.33,10.16 | 101.6,10.16 IC1.13
N$74
  Top 0.7: IC1.6 81.28,12.7 81.28,11.43 82.55,10.16 82.55,1.27 24.13,1.27 21.59,3.81 X1.1
N$75
  Top 0.7: C2.1 106.68,10.16 105.41,10.16 Q.2 104.14,10.16 IC1.14
N$76
  Top 0.7: Q1.C 6.35,121.92 6.35,115.57 Q2.C Q3.C Q4.C 15.24,91.44 15.24,87.63 16.51,86.36 16.51,83.82 8.89,83.82 | 8.89,83.82 8.89,81.28 7.62,80.01 7.62,78.74 Q6.C Q7.C Q8.C 11.43,57.15 12.7,57.15 D1.C | 8.89,83.82 Q5.C
N$77
  Top 0.7: D4.C D3.A
N$78
  Top 0.7: IC1.3 80.01,19.05 133.35,19.05 134.62,17.78 156.21,17.78 | 156.21,17.78 157.48,16.51 | R32.1 157.48,17.78 156.21,17.78 | 157.48,16.51 157.48,11.43 S3.P$3 | 157.48,16.51 S3.P$1
N$79
  Top 0.7: IC1.8 91.44,17.78 120.65,17.78 128.27,10.16 142.24,10.16 143.51,11.43 | 143.51,11.43 143.51,16.51 S2.P$1 | 143.51,11.43 S2.P$3
  Bottom 0.7: R30.2 138.43,22.86 139.7,22.86 144.78,17.78 143.51,16.51 S2.P$1
N$80  (via drill 0.7)
  Top 0.7: S1.P$3 129.54,11.43 129.54,16.51 S1.P$1 | v77.47,19.05 78.74,20.32 124.46,20.32 R29.2
  Bottom 0.7: IC1.4 78.74,19.05 v77.47,19.05 | R29.2 133.35,29.21 132.08,29.21 132.08,19.05 129.54,16.51 S1.P$1
N$81  (via drill 0.7)
  Top 0.7: v78.74,7.62 74.93,3.81 34.29,3.81 31.75,6.35 29.21,6.35 26.67,3.81 X1.2
  Bottom 0.7: IC1.9 91.44,10.16 83.82,10.16 81.28,7.62 v78.74,7.62
N$82  (via drill 0.7)
  Top 0.7: IC1.10 91.44,12.7 v83.82,12.7 | v80.01,10.16 80.01,8.89 81.28,7.62 81.28,2.54 33.02,2.54 31.75,3.81 X1.3
  Bottom 0.7: v83.82,12.7 81.28,10.16 v80.01,10.16
N$83
  Top 0.7: R1.1 5.08,128.27 7.62,128.27 Q1.B
N$84  (via drill 0.7)
  Top 0.7: Q2.B 11.43,121.92 v8.89,121.92
  Bottom 0.7: v8.89,121.92 6.35,124.46 R2.1
N$85
  Bottom 0.7: R3.1 2.54,110.49 8.89,110.49 11.43,107.95 Q3.B
N$86
  Bottom 0.7: Q4.B 11.43,102.87 10.16,102.87 6.35,106.68 R4.1
N$87
  Top 0.7: R5.1 5.08,90.17 7.62,90.17 Q5.B
N$88
  Bottom 0.7: Q6.B 11.43,78.74 12.7,80.01 12.7,82.55 10.16,82.55 6.35,86.36 R6.1
N$89
  Bottom 0.7: R7.1 2.54,72.39 8.89,72.39 11.43,69.85 Q7.B
N$90
  Bottom 0.7: Q8.B 11.43,64.77 10.16,64.77 6.35,68.58 R8.1
N$91
  Top 0.7: D2.C D1.A
N$92
  Top 0.7: D3.C D2.A
N$93  (via drill 0.7)
  Top 0.7: R31.1 153.67,22.86 144.78,22.86 143.51,24.13 | IC1.2 73.66,21.59 121.92,21.59 v130.81,30.48 | 143.51,24.13 143.51,29.21 S4.P$1 | 143.51,24.13 S4.P$3
  Bottom 0.7: v130.81,30.48 133.35,33.02 139.7,33.02 143.51,29.21 S4.P$1
N$95
  pour Bottom: 0,132.08 180.34,132.08 180.34,0 0,0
